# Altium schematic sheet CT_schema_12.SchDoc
size 146 x 119 mm
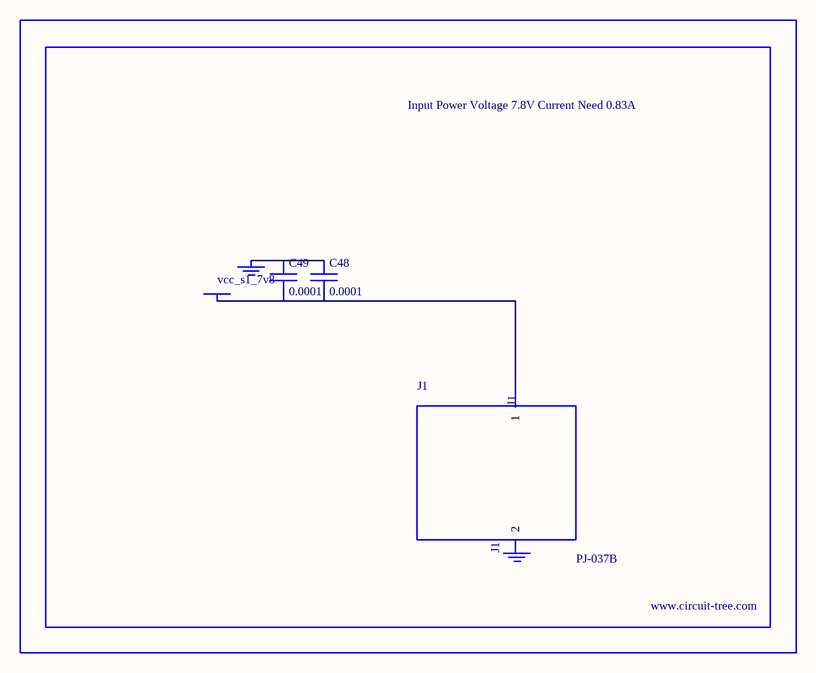
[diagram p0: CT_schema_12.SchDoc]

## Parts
BORDER11  (no value)
C48  0.0001  [EXV-9H]
C49  0.0001  [EXV-9H]
GND_INSTANCE_11_0  (no value)
GND_INSTANCE_11_1  (no value)
J1  PJ-037B  [PJ-037B_PACKAGE]
POWER_INSTANCE_11_0  vcc_s1_7v8

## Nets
NetC48_1: C48.1 C49.1 GND_INSTANCE_11_0.0(GND)
NetC48_2: C48.2 C49.2 J1.1 POWER_INSTANCE_11_0.0(PWR)

Not connected (* = marked no-connect by the designer): GND_INSTANCE_11_1 0(GND); J1 2

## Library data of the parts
BORDER11 = BORDER_PAGE11
C48 C49 = EDK107M035A9HAA
GND_INSTANCE_11_0 GND_INSTANCE_11_1 = GND
POWER_INSTANCE_11_0 = PWR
